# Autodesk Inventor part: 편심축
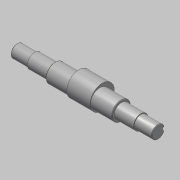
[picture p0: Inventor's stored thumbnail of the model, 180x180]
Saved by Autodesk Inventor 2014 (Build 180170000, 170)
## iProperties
Created: 2015-10
Part Number: 편심축
Document SubType Name: Modeling
Designer: mdu
Density: 7.86 g/cm^3
Material: 강철, 연강
Mass: 1327.93 g
Surface Area: 248.525 cm^2
Volume: 168.947 cm^3
Appearance: 강철
Author: mdu
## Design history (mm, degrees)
sketch "스케치1"
  geometry: L1 (-20.5, -41.331)-(-20.5, 32.669) reference; L2 (7.5, -30.031)-(7.5, 21.369) reference; L3 (135.5, -30.331)-(135.5, 21.669) reference; L4 (121.5, 21.369)-(121.5, -30.031) reference; L5 (184.5, -4.331)-(-57.5, -4.331); L6 (184.5, -4.331)-(184.5, 6.669); L7 (154.5, 8.169)-(121.5, 8.169); L8 (121.5, 8.169)-(121.5, 11.669); L9 (121.5, 11.669)-(7.5, 11.669); L10 (7.5, 11.669)-(7.5, 8.169); L11 (7.5, 8.169)-(-27.5, 8.169); L12 (-27.5, 8.169)-(-27.5, 6.669); L13 (-27.5, 6.669)-(-57.5, 6.669); L14 (-57.5, 6.669)-(-57.5, -4.331); L15 (154.5, 8.169)-(154.5, 6.669); L16 (154.5, 6.669)-(184.5, 6.669); C1 r 32.5 at (64.5, -4.331) reference; 1 further point
  constraints: 24 end point, 8 perpendicular, 5 point on line, 3 parallel, 2 collinear
  dimensions: "d1" = 25 diameter of L11 L5; "d2" = 32 diameter of L9 L5; "d3" = 22 diameter of L13 L5; "d4" = 35 distance of L10.end L11.end; "d5" = 30 distance of L12.end L13.end; "d15" = 33 distance of L7.start L7.end; "d26" = 30 distance of L15.end L6.end
revolve "회전1" sketch "스케치1" stored, may be unused: angle "d6" = 90 deg
node "작업 평면1"
sketch "스케치2"
  geometry: C1 r 16 at (0, 0) reference; C2 r 20.75 at (0, 4)
  constraints: 1 centre point, 1 vertical alignment
  dimensions: "d34" = 4 distance of C2.centre C1.centre; "d35" = 41.5 diameter of C2
extrude "돌출1" join sketch "스케치2" stored distance "d9" = 40; taper "d10" = 0 deg
chamfer "모따기1" distance "d11" = 1; stored, may be unused: second distance "d12" = 2, angle "d13" = 45 deg
node "작업 평면2"
sketch "스케치3"
  geometry: L1 (-15, -10)-(-15, 10) reference; L2 (-15, 3)-(0, 3); L3 (0, -3)-(-15, -3); A1 r 3 centre (0, 0) between (0, -3) and (0, 3); 2 further points
  constraints: 4 end point, 2 perpendicular, 2 point on circle, 2 point on line, 2 tangent, 1 centre point, 1 horizontal alignment, 1 midpoint
  dimensions: "d16" = 18 dimension on A1 L1; "d17" = 6 distance between parallel lines of L3 L2
extrude "돌출2" cut sketch "스케치3" distance "d18" = 3.5; taper "d19" = 0 deg
node "작업 평면3"
node "솔리드1"
mirror "대칭1"
node "참조1"
node "참조2"
node "참조3"
node "참조4"
node "참조5"
other parameters: "d30" = 35
